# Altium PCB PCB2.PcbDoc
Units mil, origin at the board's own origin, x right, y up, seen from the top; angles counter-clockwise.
Board outline 810 x 2240 mil, 2 copper layers (GND, 3V3); 41 components, 27 nets, 142 pads, 8 vias.
Unrouted connection lines stored in the file: 76.
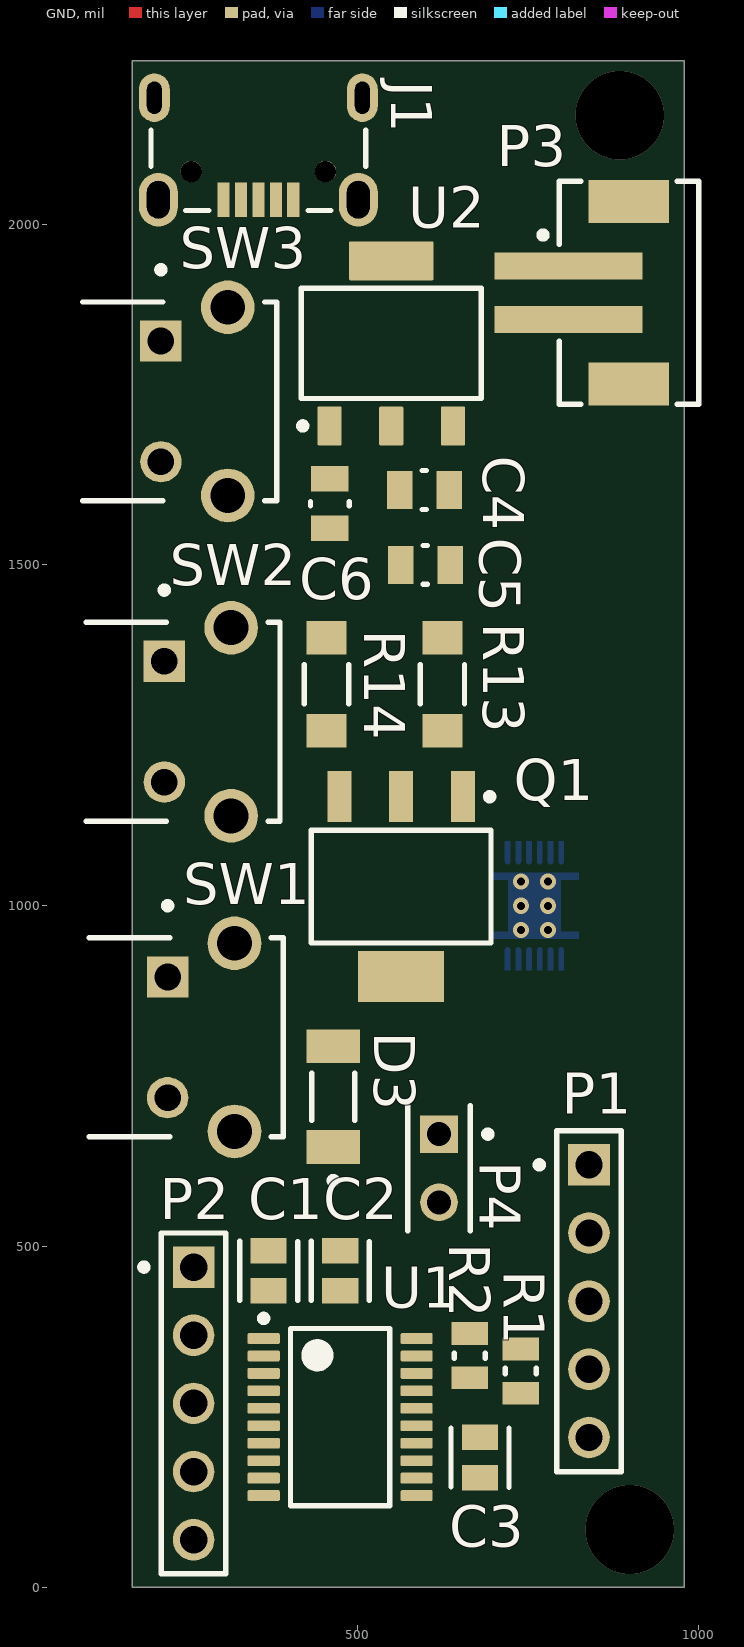
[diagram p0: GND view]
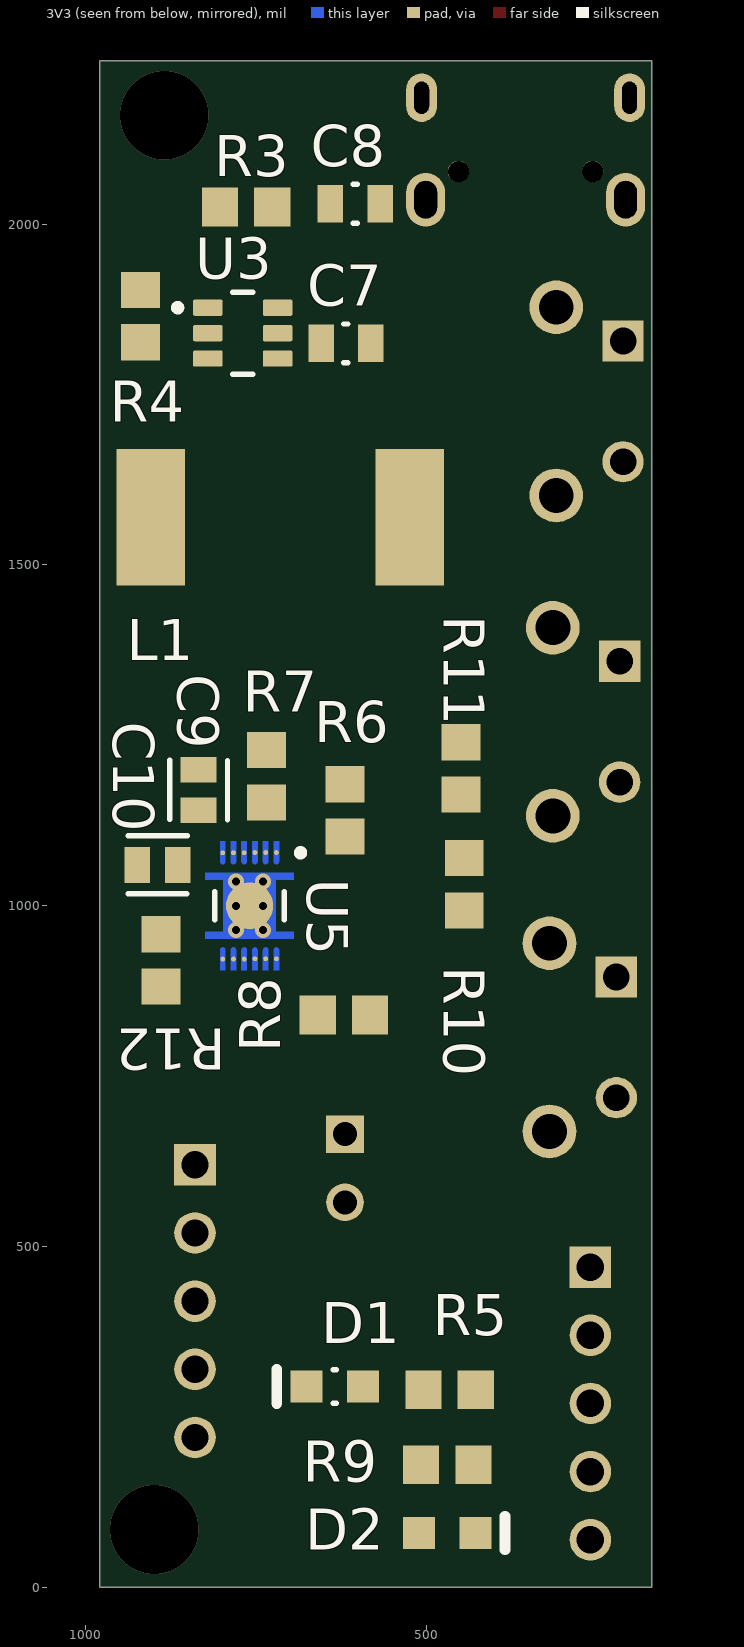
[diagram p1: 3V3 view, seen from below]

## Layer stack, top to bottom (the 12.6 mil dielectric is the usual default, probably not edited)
Top Solder: solder mask 0.4, Solder Resist, Dk 3.5
GND: signal copper 1.4
Dielectric 1: dielectric 12.6, FR-4, Dk 4.8
3V3: signal copper 1.4
Bottom Solder: solder mask 0.4, Solder Resist, Dk 3.5

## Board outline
170,0 980,0 980,2240 170,2240

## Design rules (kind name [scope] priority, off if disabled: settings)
Clearance [All] p1: gap=8 ignorepadtopadclearanceinfootprint=FALSE except(6: Arc-Arc Arc-Track Arc-SMDPad Arc-THPad Track-Track Track-SMDPad Track-THPad SMDPad-SMDPad SMDPad-THPad THPad-THPad Fill-Fill Fill-Poly Fill-Region Poly-Poly Poly-Region Region-Region; 10: Fill-Hole Poly-Hole Region-Hole)
PolygonConnect [All] p1: connectstyle=Relief reliefconductorwidth=10 reliefentries=4 polygonreliefangle="90 Angle" airgapwidth=10
RoutingVias [All] p1: holewidth=28 width=50 viastyle="Through Hole" minholewidth=28 minwidth=50 maxholewidth=28 maxwidth=50
SolderMaskExpansion [All] p1: expansion=4 istentingtop=FALSE
Width [All] p1: maxlimit=10 minlimit=10 preferedwidth=10
30 further rules are at their usual default settings.

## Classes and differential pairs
component class "Power Supply": C4 C5 C6 C7 C8 L1 R3 R4 U2 U3
component class MotorControl: D3 P4 Q1 R13 R14
component class MCU: C1 C2 C3 P1 P2 R1 R2 SW1 SW2 SW3 U1
component class BatteryControl: J1 P3 U4 U5

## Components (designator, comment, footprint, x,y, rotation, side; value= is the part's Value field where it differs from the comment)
C1 "10 uF" FP-C0805C-DG-MFG 370,464.53 r90 top value=10uF
C2 "0.1 uF" FP-C0805C-DG-MFG 475,464.53 r90 top value=10uF
C3 "1.1 nF" FP-C0805C-DG-MFG 680.3,190.47 r270 top value=10uF
C4 "4.7uF" FP-CC0805-0_85-MFG 598.58,1610 r180 top value="100 nF"
C5 "470nF" FP-CC0805-0_85-MFG 600,1500 r180 top value="100 nF"
C6 "4.7uF" FP-CC0805-0_85-MFG 460,1590 r270 top value="100 nF"
C7 "1uF" FP-CC0805-0_85-MFG 618.58,1825 r180 bottom value="100 nF"
C8 "4.7uF" FP-CC0805-0_85-MFG 605,2030 r0 bottom value="100 nF"
C9 "0.47 uF" FP-C0805C-DG-MFG 835,1170 r90 bottom value=10uF
C10 "1 nF" FP-C0805C-DG-MFG 895,1060 r0 bottom value=10uF
D1 "LTST-C170KRKT" LTST-C170KRKT_V 635,295 r0 bottom
D2 "HSMG-C170" AVAG-HSMX-C170_V 470,80 r180 bottom
D3 "LS4148-GS18" FP-6_560-5006_01-4-MFG 465,720 r90 top value=4pF
J1 "629105150521" 629105150521 355,2150 r180 top
L1 "Bourns SRU1048-100Y" "Bourns SRU1048-100Y-Footprint-1" 715,1565 r180 bottom
P1 "77311-462K05LF" FCI-77311-5_V 840,420 r270 top
P2 "77311-462K05LF" FCI-77311-5_V 260,270 r270 top
P3 "620302124022" 620302124022 898.58,1899.37 r90 top
P4 "5-146280-2" TECO-5-146280-2_V 620,615 r270 top
Q1 "BSP89" INF-PG-SOT223_SC-73_M 564.45,1028.11 r270 top
R1 "47k" RESC2013X50X30LL20T20 740,317.52 r90 top
R2 "1k" RESC2013X50X30LL20T20 665,340 r90 top
R3 "Resistor 1k +/-1% 0805 125 mW" RESC2013X70X40ML20T20 765,2025 r180 bottom value=1M
R4 "Resistor 1k +/-1% 0805 125 mW" RESC2013X70X40ML20T20 920,1865 r270 bottom value=71.5k
R5 "Resistor 1k +/-1% 0805 125 mW" RESC2013X70X40ML20T20 466.61,290 r180 bottom value=470
R6 "Resistor 1k +/-1% 0805 125 mW" RESC2013X70X40ML20T20 620,1140 r90 bottom value=4.7k
R7 "Resistor 1k +/-1% 0805 125 mW" RESC2013X70X40ML20T20 735,1190 r90 bottom value=4.7k
R8 "Resistor 1k +/-1% 0805 125 mW" RESC2013X70X40ML20T20 621.61,840 r180 bottom value=10k
R9 "Resistor 1k +/-1% 0805 125 mW" RESC2013X70X40ML20T20 470,180 r180 bottom value=470
R10 "Resistor 1k +/-1% 0805 125 mW" RESC2013X70X40ML20T20 445,1031.61 r270 bottom value=10k
R11 "Resistor 1k +/-1% 0805 125 mW" RESC2013X70X40ML20T20 450,1201.61 r270 bottom value=10k
R12 "Resistor 1k +/-1% 0805 125 mW" RESC2013X70X40ML20T20 890,920 r270 bottom value=0.01
R13 "220" FP-CR1206-MFG 625,1325 r270 top
R14 "10k" FP-CR1206-MFG 455,1325 r270 top
SW1 "1825027-5" FP-1825027-5-0 224.92,807.01 r270 top
SW2 "1825027-5" FP-1825027-5-0 220,1270 r270 top
SW3 "1825027-5" FP-1825027-5-0 215,1740 r270 top
U1 "MSP430G2553IPW20" PW0020A_L 475,250 r0 top
U2 "LM340MP-5.0/NOPB" DCY0004A_L 550,1825 r90 top
U3 "TLV61046ADBVT" FP-DBV0006A-MFG 770,1840 r180 bottom
U5 "BQ27441DRZR-G1A" FP-DRZ0012A-MFG 760,1000 r0 bottom

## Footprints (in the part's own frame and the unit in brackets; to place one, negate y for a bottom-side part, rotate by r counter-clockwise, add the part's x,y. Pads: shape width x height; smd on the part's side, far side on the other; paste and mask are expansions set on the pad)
620302124022 [mm] "2.00mm SMT Male Vertical Shrouded Header, 2p"
  rect 1x5.5 smd: 1(1,2.25) 2(-1,2.25)
  rect 1.6x3 smd: MP1(-3.4,0) MP2(3.4,0)
  silkscreen extent -4.15,-2.6 4.15,3.32, body extent -4,-2.5 4,4.51, height 6.77
629105150521 [mm] "Micro USB 2.0 SMT Type B Horizontal 5 Contacts High Current"
  rect 0.45x1.3 smd: 1(-1.3,2.9) 2(-0.65,2.9) 3(0,2.9) 4(0.65,2.9) 5(1.3,2.9)
  round 0.8 hole 0.8 unplated: MH1(-2.5,1.85) MH2(2.5,1.85)
  oval 1.15x1.8 hole 0.55 slot 1.2 at 90 deg: Shell(-3.875,-0.9) Shell(3.875,-0.9)
  oval 1.45x2 hole 0.85 slot 1.4 at 90 deg: Shell(-3.725,2.9) Shell(3.725,2.9)
  silkscreen extent -4,0.3 4,3.3, body extent -4,-3.3 4,3.3, height 2.75
AVAG-HSMX-C170_V [mm] "SMD, 2-Leads, Body 2x1.25mm, Height 0.8mm"
  rect 1.2x1.2 smd: 1(-1.05,0) 2(1.05,0)
  silkscreen extent 2.15,-0.63 2.15,0.63, body extent -1,-0.63 1,0.63, height 0.8
"Bourns SRU1048-100Y-Footprint-1" [mil]
  rect 100x200 smd: 1(190,5) 2(-190,5)
  body extent -197,-197 197,197, height 189
DCY0004A_L [mm] "SOT223, 4-Leads, Body 6.7x3.7mm, Pitch 2.3mm, IPC High Density"
  rrect11% 1.45x0.9 smd: 1(-3.075,2.3) 2(-3.075,0) 3(-3.075,-2.3)
  rrect7% 1.45x3.15 smd: 4(3.075,0)
  silkscreen extent -3.2,-3.35 2.05,3.42, body extent -3.5,-3.25 3.5,3.25, height 1.62
FCI-77311-5_V [mm] "THD, 5-Leads, Body 12.7x2.4mm, Pitch 2.54mm"
  rect 1.55x1.55 hole 1.02: 1(-5.08,0)
  round 1.55 hole 1.02: 2(-2.54,0) 3(0,0) 4(2.54,0) 5(5.08,0)
  silkscreen extent -6.35,-1.97 6.35,1.2, body extent -6.35,-1.2 6.35,1.2, height 16.24
FP-6_560-5006_01-4-MFG [mm]
  rect 1.25x2 smd paste+0 mask+0: 1(-1.875,0) 2(1.875,0)
  silkscreen extent -3.25,-0.8 0.87,0.8, body extent -2.6,-1.1 2.6,1.1, height 0.25
FP-1825027-5-0 [mm]
  rect 1.54x1.54 hole 0.99 paste-1000 mask+0: 1(-2.25,-0.075)
  round 1.54 hole 0.99 paste-1000 mask+0: 2(2.25,-0.075)
  round 2 hole 1.3 paste-1000 mask+0: 3(-3.505,2.415) 4(3.505,2.415)
  silkscreen extent -5.03,-3 3.7,4.23, body extent -4.6,-4.34 4.6,4.33, height 0.25
FP-C0805C-DG-MFG [mm]
  rect 0.95x1.35 smd paste+0 mask+0: 1(-0.75,0) 2(0.75,0)
  silkscreen extent -1.11,-1.08 1.1,1.07, body extent -1,-0.63 1,0.63, height 1.4
FP-CC0805-0_85-MFG [mm]
  rect 0.95x1.4 smd paste+0 mask+0: 1(-0.925,0) 2(0.925,0)
  silkscreen extent -0.08,-0.72 0.08,0.72, body extent -1.6,-1.05 1.6,1.05, height 0.25
FP-CR1206-MFG [mm]
  rect 1.25x1.5 smd paste+0 mask+0: 1(-1.725,0) 2(1.725,0)
  silkscreen extent -0.72,-0.82 0.72,0.82, body extent -2.45,-0.92 2.45,0.92, height 0.25
FP-DBV0006A-MFG [mm]
  rrect17% 1.1x0.6 smd paste+0 mask+0: 1(-1.3,0.95) 2(-1.3,0) 3(-1.3,-0.95) 4(1.3,-0.95) 5(1.3,0) 6(1.3,0.95)
  silkscreen extent -2.55,-1.53 0.38,1.53, body extent -1.4,-1.45 1.4,1.45, height 1.45
FP-DRZ0012A-MFG [mm]
  round 0.18 smd paste-1000 mask+0: 1(-1,-1.985) 2(-0.6,-1.985) 3(-0.2,-1.985) 4(0.2,-1.975) 5(0.6,-1.975) 6(1,-1.975) 7(1,1.985) 8(0.6,1.985) 9(0.2,1.985) 10(-0.2,1.975) 11(-0.6,1.975) 12(-1,1.975)
  round 1.755 smd paste-1000 mask+0: 13(0,0)
  GND region: -1.65,1.225 1.65,1.225 1.65,0.975 0.975,0.975 0.975,-0.975 1.65,-0.975 1.65,-1.225 -1.65,-1.225 -1.65,-0.975 -0.975,-0.975 -0.975,0.975 -1.65,0.975 -1.65,1.225
  GND region: -0.9,2.4 -0.9,1.65 -0.913,1.6 -0.95,1.563 -1,1.55 -1,1.55 -1.038,1.558 -1.071,1.579 -1.092,1.612 -1.1,1.65 -1.1,1.65 -1.1,2.4
  GND region: -0.5,2.4 -0.5,1.65 -0.513,1.6 -0.55,1.563 -0.6,1.55 -0.6,1.55 -0.638,1.558 -0.671,1.579 -0.692,1.612 -0.7,1.65 -0.7,1.65 -0.7,2.4
  GND region: -0.1,2.4 -0.1,1.65 -0.113,1.6 -0.15,1.563 -0.2,1.55 -0.2,1.55 -0.238,1.558 -0.271,1.579 -0.292,1.612 -0.3,1.65 -0.3,1.65 -0.3,2.4
  GND region: 0.3,2.4 0.3,1.65 0.287,1.6 0.25,1.563 0.2,1.55 0.2,1.55 0.162,1.558 0.129,1.579 0.108,1.612 0.1,1.65 0.1,1.65 0.1,2.4
  GND region: 0.7,2.4 0.7,1.65 0.687,1.6 0.65,1.563 0.6,1.55 0.6,1.55 0.562,1.558 0.529,1.579 0.508,1.612 0.5,1.65 0.5,1.65 0.5,2.4
  GND region: 1.1,2.4 1.1,1.65 1.087,1.6 1.05,1.563 1,1.55 1,1.55 0.962,1.558 0.929,1.579 0.908,1.612 0.9,1.65 0.9,1.65 0.9,2.4
  GND region: 0.9,-2.4 0.9,-1.65 0.908,-1.612 0.929,-1.579 0.962,-1.558 1,-1.55 1,-1.55 1.038,-1.558 1.071,-1.579 1.092,-1.612 1.1,-1.65 1.1,-1.65 1.1,-2.4
  GND region: 0.5,-2.4 0.5,-1.65 0.508,-1.612 0.529,-1.579 0.562,-1.558 0.6,-1.55 0.6,-1.55 0.638,-1.558 0.671,-1.579 0.692,-1.612 0.7,-1.65 0.7,-1.65 0.7,-2.4
  GND region: 0.1,-2.4 0.1,-1.65 0.108,-1.612 0.129,-1.579 0.162,-1.558 0.2,-1.55 0.2,-1.55 0.238,-1.558 0.271,-1.579 0.292,-1.612 0.3,-1.65 0.3,-1.65 0.3,-2.4
  GND region: -0.3,-2.4 -0.3,-1.65 -0.292,-1.612 -0.271,-1.579 -0.238,-1.558 -0.2,-1.55 -0.2,-1.55 -0.162,-1.558 -0.129,-1.579 -0.108,-1.612 -0.1,-1.65 -0.1,-1.65 -0.1,-2.4
  GND region: -0.7,-2.4 -0.7,-1.65 -0.692,-1.612 -0.671,-1.579 -0.638,-1.558 -0.6,-1.55 -0.6,-1.55 -0.562,-1.558 -0.529,-1.579 -0.508,-1.612 -0.5,-1.65 -0.5,-1.65 -0.5,-2.4
  GND region: -1.1,-2.4 -1.1,-1.65 -1.092,-1.612 -1.071,-1.579 -1.038,-1.558 -1,-1.55 -1,-1.55 -0.962,-1.558 -0.929,-1.579 -0.908,-1.612 -0.9,-1.65 -0.9,-1.65 -0.9,-2.4
  silkscreen extent -2.02,-2.1 1.3,0.53, body extent -1.25,-2 1.25,2, height 1
INF-PG-SOT223_SC-73_M [mm] "SOT223, 4-Leads, Body 6.5x3.5mm, Pitch 2.3mm, IPC Low Density"
  rect 1.9x0.9 smd: 1(-3.35,2.3) 2(-3.35,0) 3(-3.35,-2.3)
  rect 1.9x3.2 smd: 4(3.35,0)
  silkscreen extent -3.47,-3.35 2.1,3.43, body extent -1.85,-3.35 1.85,3.35, height 1.8
LTST-C170KRKT_V [mm] "SMD, 2-Leads, Body 2x1.25mm"
  rect 1.2x1.2 smd: 1(-1.05,0) 2(1.05,0)
  silkscreen extent -0.05,-0.64 2.16,0.64, body extent -1,-0.63 1,0.63, height 1.2
PW0020A_L [mm] "SOP, 20-Leads, Body 6.6x4.5mm, Pitch 0.65mm, IPC High Density"
  rrect25% 1.2x0.4 smd: 1(-2.85,2.925) 2(-2.85,2.275) 3(-2.85,1.625) 4(-2.85,0.975) 5(-2.85,0.325) 6(-2.85,-0.325) 7(-2.85,-0.975) 8(-2.85,-1.625) 9(-2.85,-2.275) 10(-2.85,-2.925) 11(2.85,-2.925) 12(2.85,-2.275) 13(2.85,-1.625) 14(2.85,-0.975) 15(2.85,-0.325) 16(2.85,0.325) 17(2.85,0.975) 18(2.85,1.625) 19(2.85,2.275) 20(2.85,2.925)
  silkscreen extent -2.97,-3.3 1.85,3.8, body extent -3.21,-3.25 3.21,3.25, height 1
RESC2013X50X30LL20T20 [mm] "Chip Resistor, 2-Leads, Body 2.00x1.25mm, IPC High Density"
  rect 0.85x1.35 smd: 1(-0.825,0) 2(0.825,0)
  silkscreen extent -0.1,-0.58 0.1,0.58, body extent -1.1,-0.72 1.1,0.72, height 0.5
RESC2013X70X40ML20T20 [mm] "Chip Resistor, 2-Leads, Body 2.2x1.35mm, IPC Low Density"
  rect 1.35x1.45 smd: 1(-0.975,0) 2(0.975,0)
  body extent -1.1,-0.67 1.1,0.67, height 0.7
TECO-5-146280-2_V [mm] "Connector, 2-Leads, Body 4.67x2.34mm, Pitch 2.54mm"
  rect 1.4x1.4 hole 0.89: 1(-1.27,0)
  round 1.4 hole 0.89: 2(1.27,0)
  silkscreen extent -2.33,-1.17 2.33,1.94, body extent -2.34,-1.17 2.34,1.17, height 5.33

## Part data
C1 C2 C3 C9 C10: library part CMP-2007-03243-2, "CAP CER 10UF 10V X5R 0805", 3DS Part Number=220-00001, Capacitance=10uF, Manufacturer=Kemet, Manufacturer Part Number=C0805C106K8PACTU, Package=C0805C-DG, Temperature="-55°C to +85°C", Temperature Characteristic=X5R, Temperature Coefficient=15%, Temperature Range High=+85°C, Temperature Range Low=-55°C, Tolerance=10%, Voltage=10V
C4 C5 C6 C7 C8: library part CMP-03422-000499-1, "CAP CER 0.1UF 50V X7R 0805", Capacitance="100 nF", Manufacturer=Yageo, Manufacturer Part Number=CC0805KRX7R9BB104, Package=CC0805-0.85, Temperature="-30°C to +85°C", Temperature Characteristic=X7R, Temperature Range High=+85°C, Temperature Range Low=-30°C, Tolerance=0.1, Voltage Rating="50 V"
D1: library part CMP-2000-07593-1, "LED Red, 75 mW, 54 mcd, -55 to 85 degC, 2-Pin SMD, RoHS, Tape and Reel", Case Code (Imperial)=0805, Case Code (Metric)=2012, Colour=Red, Forward Current=30mA, Forward Voltage=2V, Lens Colour=Colorless, Manufacturer=Lite-On, Max Operating Temperature=85degC, Min Operating Temperature=-55degC, Package Description="2-Pin Surface Mount Device, Body 2 x 1.25 mm", Package Quantity=1, Package Reference=C170KRKT, Power Dissipation=75mW, Test Current=20mA
D2: library part CMP-2000-05062-1, "Chip LED, Green, 2.2 V, -40 to 85 degC, 2-Pin SMD, Pb-Free, Tape and Reel", Forward Current If=20mA, Forward Voltage=2.2V, Forward Voltage VF Max=2.6V, LED Colour=Green, Manufacturer=Avago, Operating Temperature Max=85degC, Operating Temperature Min=-30degC, Operating Temperature Range=-30degCto+85degC, Opto Case Style=SMD, Package Description="2-Pin Surface Mount Device, Body 2 x 1.25 mm, Height 0.8 mm", Package Reference=HSMX-C170, Storage Temperature Min=-40degC
D3: library part CMP-02539-000014-1, "DIODE GEN PURP 75V 150MA SOD80", Capacitance=4pF, Forward Current=300mA, Manufacturer=Vishay, Max Junction Temp=+175°C, Max Repetitive Reverse Voltage=100V, Max Surge Forward Current=2A, Package=6.560-5006.01-4, Peak Reverse Current=5uA, Reverse Voltage=75V, Temperature="to +175°C"
J1: library part CMP-1502-03252-1, "Micro USB 2.0 Type B Receptacle WR-COM, Horizontal, SMT, with Pegs, High Current at Pin 1 & Pin 5", Contact Resistance=30mOhm, Manufacturer="Wurth Elektronik", Operating Temperature=-40to85degC, Rated Current=3A, Working Voltage=30VAC
L1: library part CMP-006-00021-1, "Inductor"
P1 P2: library part CMP-1698-00006-1, "Male Header, Pitch 2.54 mm, 1 x 5 Position, Height 16.24 mm, Tail Length 3.05 mm,  / -65 to 125 degC, RoHS, Tape and Reel", Current Rating="1 A", Max Operating Temperature=85degC, Min Operating Temperature=-25degC, Package Quantity=500
P3: library part CMP-1502-00660-1, "Male Shrouded Header WR-WTB, SMT, Vertical, pitch 2 mm, 1 x 2 position", Contact Resistance=20mOhm, Manufacturer="Wurth Elektronik", Operating Temperature=-25to85degC, Working Voltage=100VAC
P4: library part CMP-2000-07492-1, "Male Header, Pitch 2.54 mm, 1 x 2 Position, Height 8.21 mm, Tail Length 3.05 mm, -65 to 105 degC, RoHS, Bulk", Case\/Package=100, Colour=Black, Current Rating=3A, Flammability Rating=UL94V-0, High Temperature Housing=Yes, Manufacturer="TE Connectivity", Max Current Rating=5A, Max Operating Temperature=105degC, Min Operating Temperature=-65degC, Package Description="Male Header, Pitch 2.54 mm, 1 x 2 Position, Height 8.21 mm, Tail Length 3.05 mm", Package Quantity=500
Q1: library part CMP-1149-00010-1, "N-Channel SIPMOS Small-Signal-Transistor, 240 V VDS, 0.35 A ID, -55 to 150 degC, PG-SOT223 (SC-73), Reel, Green", Manufacturer=Infineon
R1 R2: library part CMP-2001-04896-1, Manufacturer="Vishay Dale", Part Number=CRCW08050000Z0EA
R3 R4 R5 R6 R7 R8 R9 R10 R11 R12: library part CMP-009-00010-4, "Chip Resistor, 1 KOhm, +/- 1%, 0.125 W, -55 to 155 degC, 0805 (2013 Metric)", Case/Package=0805, Max Operating Temperature=155°C, Min Operating Temperature=-55°C, Power=125mW, Tolerance=1%, Voltage Rating=150V
R13 R14: library part CMP-07231-003158-1, "Thick Film Chip Resistors 1206 330Ω 0.25W 1% 100ppm/°C", Case Code (Imperial)=1206, Case Code (Metric)=3216, Max Operating Temperature=155°C, Max Power Dissipation=250mW, Min Operating Temperature=-55°C, Package Quantity=5000, Resistance=330R, Temperature Coefficient=100ppm/°C, Tolerance=1%, Voltage Rating=200V
SW1 SW2 SW3: library part CMP-2000-05514-2, "SWITCH TACTILE SPST-NO 0.05A 24V", Contact Current Rating=50mA, Contact Resistance=100mΩ, Manufacturer="TE Connectivity", Operating Force=160gf, Temperature="-35°C to +85°C", Temperature Range High=+85°C, Temperature Range Low=-35°C, Voltage Rating Dc=24V
U1: library part CMP-0365-00585-2, "16 MHz Mixed Signal Microcontroller with 16 KB Flash, 512 B SRAM and 24 GPIOs, -40 to 85 degC, 20-pin SOP (PW), Green (RoHS & no Sb/Br)", Frequency(MHz)=16, Manufacturer="Texas Instruments", Temp Sensor=Yes
U2: library part CMP-0062-01784-3, "Series 3-Terminal Positive Regulators, 4-pin SOT-223, Pb-Free", Manufacturer="Texas Instruments", PackageTopMarking=XYTT*N00A, PowerWise=N
U3: library part CMP-04918-000055-1, "IC REG BOOST ADJ SOT23-6", Manufacturer="Texas Instruments", Max Junction Temp=+125°C, Max Supply Voltage=5.5V, Min Supply Voltage=1.8V, Nominal Supply Current=110uA, Output Current=980mA, Output Voltage=3.3-28V, Package=DBV0006A, Switching Frequency=1050kHz, Temperature="-40°C to +125°C", Temperature Range Low=-40°C
U5: library part CMP-04911-000008-1, "IC BATT FUEL GAUGE LI-ION 12SON", Ambient Temperature Range High=+85°C, Ambient Temperature Range Low=-40°C, Manufacturer="Texas Instruments", Max Supply Voltage=4.5V, Min Supply Voltage=2.45V, Nominal Supply Current=93uA, Output Voltage=1.8V, Package=DRZ0012A, Temperature="-40°C to +85°C"

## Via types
v1: diameter 23.62, hole 11.81, GND to 3V3, 6 vias
v2: diameter 130, hole 130, GND to 3V3, 2 vias

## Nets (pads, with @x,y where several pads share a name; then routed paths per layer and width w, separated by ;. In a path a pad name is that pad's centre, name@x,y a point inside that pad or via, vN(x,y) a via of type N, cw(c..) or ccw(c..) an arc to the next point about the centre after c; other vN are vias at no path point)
+3.3V: C4.1 C5.1 U2.3
+3V3: C1.1 C2.1 P1.1 R1.2 R6.2 R7.2 R8.2 U1.1
+5V: J1.1
+12V: C8.2 D3.1 P4.2 R3.2 U3.5
+BATT: C10.1 P3.2 R12.1 U5.6 U5.8
CHG: D1.2
"CTL FAN": P1.5 R13.1 U1.2
GND: C1.2 C2.2 C3.2 C4.2 C5.2 C6.2 C7.2 C8.1 C9.2 C10.2 D2.2 J1.5 P1.2 P3.1 R2.2 R4.1 R10.1 R11.1 R14.1 U1.20 U2.2 U2.4 U3.2 U5.3
GPBATT: R8.1 U5.12
"I2C SCL": P2.4 R7.1 U1.9 U5.2
"I2C SDA": P2.5 R6.1 U1.10 U5.1
NetC9_1: C9.1 U5.5
NetD1_1: D1.1 R5.1
NetD2_1: D2.1 R9.1
NetD3_2: D3.2 P4.1 Q1.2 Q1.4
NetL1_2: L1.2 U3.1
NetQ1_1: Q1.1 R13.2
NetQ1_3: Q1.3 R14.2
NetR3_1: R3.1 R4.2 U3.3
NetR10_2: R10.2
NetR11_2: R11.2
P1.1: P2.1 U1.3
P1.3: P2.2 U1.5
P1.4: P2.3 U1.6
TDIO: C3.1 P1.4 R1.1 U1.16
TEST: P1.3 R2.1 U1.17
VSYS: C6.1 C7.1 L1.1 R5.2 R9.2 R12.2 U2.1 U3.6 U5.7
pads on no net: J1.2 J1.3 J1.4 J1.MH1 J1.MH2 J1.Shell P3.MP1 P3.MP2 SW1.1 SW1.2 SW1.3 SW1.4 SW2.1 SW2.2 SW2.3 SW2.4 SW3.1 SW3.2 SW3.3 SW3.4 U1.4 U1.7 U1.8 U1.11 U1.12 U1.13 U1.14 U1.15 U1.18 U1.19 U3.4 U5.4 U5.9 U5.10 U5.11 U5.13
copper on no net:
  other v1: 740.32,964.57 779.68,964.57 740.32,1000 779.68,1000 740.32,1035.43 779.68,1035.43
  other v2: 900,85 885,2160

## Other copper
GND:
  text "U4 has no footprint" at 220,2609.99 h60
